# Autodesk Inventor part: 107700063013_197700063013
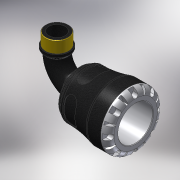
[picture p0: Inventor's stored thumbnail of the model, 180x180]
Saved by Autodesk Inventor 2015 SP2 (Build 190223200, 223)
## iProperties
Created: 2016-12
Part Number: 107700063013_197700063013
Material: PVC-Piping
Description: PLASSON 90° ELBOW WITH MALE INTEGRAL BRASS 63X1.1/4" SERIES 1
Document SubType Name: Modeling
Designer: KIM
Mass: 664.223 g
Surface Area: 733.008 cm^2
Volume: 474.445 cm^3
Density: 1.4 g/cm^3
Appearance: Black Cast
Author: KIM
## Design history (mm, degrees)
derived "1077.ipt"
feature "Solid1::1077.ipt"
tag "TaggingFeature1"
body "Solid1"
other parameters: "d1" = 37.8, "d2" = 63, "d3" = 78.75, "d4" = 103, "d8" = 87.55, "d13" = 9.7, "d14" = 9.7, "d15" = 0, "d17" = 360 deg, "d19" = 8 deg, "d20" = 1.26, "d21" = 1.26, "d22" = 8 deg, "d24" = 0, "d26" = 360 deg, "d33" = 10.3, "d43" = 80.34, "d51" = 1.03, "d54" = 22.05, "d55" = 13.86, "d57" = 19.012, "d58" = 0, "d74" = 0, "d82" = 1.26, "d115" = 360 deg, "d207" = 90 deg, "d228" = 18.7425, "d247" = 2.06, "d248" = 5.4, "d268" = 48.1525, "d269" = 5.4, "d270" = 143, "d276" = 41.91, "d277" = 21, "d278" = 46.101, "d279" = 74, "d280" = 27.3, "d281" = 6.2865, "d283" = 37.719, "d286" = 0, "d287" = 0, "d288" = 29.337, "d290" = 21.3105, "d292" = 30 deg, "d294" = 4.191, "d296" = 30 deg, "d_" = 63, "E_" = 103, "A_" = 143, "A_1" = 74, "l_2" = 21, "R_" = 41.91, "d9" = 12.125, "d11" = 103, "d12" = 78.75, "d289" = 29.337
